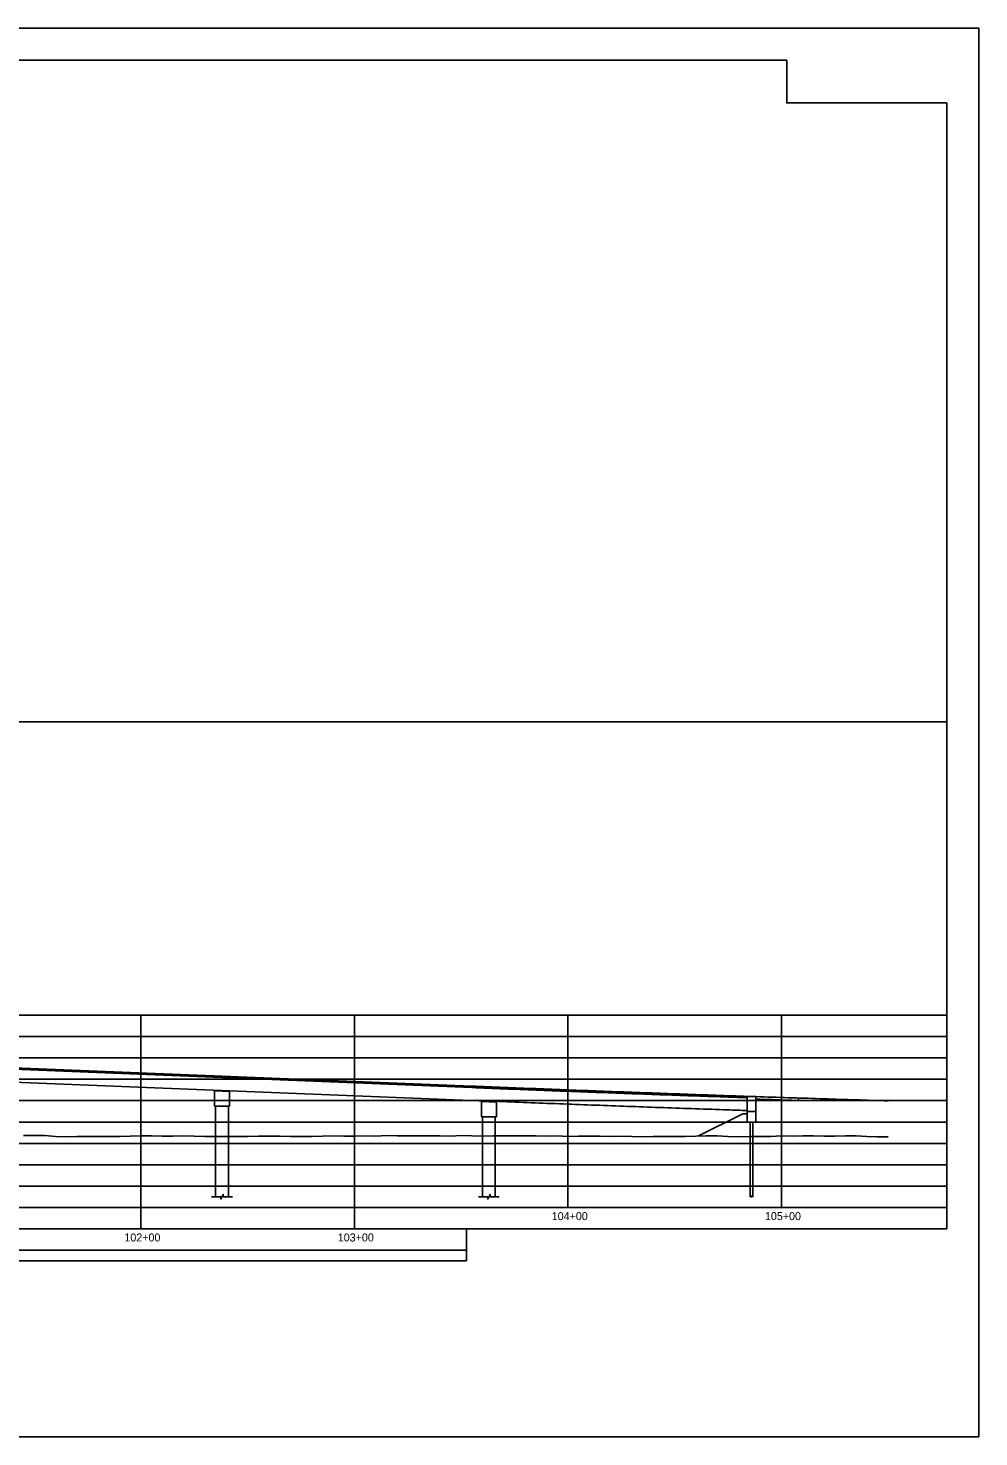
# Model space of a CAD drawing. Extents: x -464 to 4306, y -1372 to 300.
# Drawn here: x 3861 to 4306, y -1372 to -712 of the extents above; entities that cross this region are included whole.
import ezdxf

# ---------------------------------------------------------------- set-up
doc = ezdxf.new("R2010")
doc.units = 0
for name, color, linetype in [('BR_AUTO DIMENSION', 7, 'Continuous'), ('BR_BORDER LINES', 7, 'Continuous'), ('BR_GRID LINES', 7, 'Continuous'), ('BR_TEXT', 7, 'Continuous'), ('Mis Ground Lines', 7, 'Continuous'), ('Miscellaneous Lines', 7, 'Continuous'), ('NOPLOT', 7, 'Continuous'), ('Sheet Plot Border Outside CELL', 7, 'Continuous'), ('sub interior bent cap lines', 7, 'Continuous'), ('Sub Interior Bent Footing Line', 7, 'Continuous'), ('Sub Steel Pile Lines', 7, 'Continuous'), ('Sup Concrete Girder Lines', 7, 'Continuous'), ('Sup Concrete Slab Lines', 7, 'Continuous')]:
    doc.layers.add(name, color=color, linetype=linetype)

msp = doc.modelspace()

# ---------------------------------------------------------------- linework, layer by layer
at = {"layer": 'BR_AUTO DIMENSION'}
for points in [[(3946.62, -1259.94), (3950.94, -1259.94), (3950.94, -1261.06), (3952.06, -1258.83), (3952.06, -1259.94), (3956.37, -1259.94)], [(4071.62, -1259.94), (4075.94, -1259.94), (4075.94, -1261.06), (4077.06, -1258.83), (4077.06, -1259.94), (4081.37, -1259.94)], [(4200.36, -1259.83), (4199.66, -1259.83), (4199.66, -1260.15), (4199.34, -1259.51), (4199.34, -1259.83), (4198.64, -1259.83)]]:
    msp.add_lwpolyline(points, dxfattribs=at)
at = {"layer": 'BR_BORDER LINES'}
msp.add_line((3286, -1037.44), (4291, -1037.44), dxfattribs=at)
at = {"layer": 'BR_GRID LINES'}
for p, q in [((3286, -1174.94), (4291, -1174.94)), ((3913.5, -1274.94), (3913.5, -1174.94)), ((4013.5, -1274.94), (4013.5, -1174.94)), ((4113.5, -1264.94), (4113.5, -1174.94)), ((4213.5, -1264.94), (4213.5, -1174.94)), ((3286, -1184.94), (4291, -1184.94)), ((3286, -1194.94), (4291, -1194.94)), ((3286, -1204.94), (4291, -1204.94)), ((3286, -1214.94), (4291, -1214.94)), ((3286, -1224.94), (4291, -1224.94)), ((3286, -1234.94), (4291, -1234.94)), ((3286, -1244.94), (4291, -1244.94)), ((3286, -1254.94), (4291, -1254.94)), ((3286, -1264.94), (4291, -1264.94)), ((3286, -1274.94), (4066, -1274.94)), ((3286, -1284.94), (4066, -1284.94))]:
    msp.add_line(p, q, dxfattribs=at)
at = {"layer": 'Mis Ground Lines'}
for p, q in [((4195.5, -1221.04), (4174.44, -1231.57)), ((4197.5, -1221.04), (4195.5, -1221.04))]:
    msp.add_line(p, q, dxfattribs=at)
for points in [[(3858.5, -1231.34), (3863.5, -1231.19), (3868.5, -1231.27), (3873.5, -1231.78), (3878.5, -1231.85), (3883.5, -1231.8), (3888.5, -1231.75), (3893.5, -1231.69), (3898.5, -1231.67), (3903.5, -1231.66), (3908.5, -1231.57), (3913.5, -1231.47), (3918.5, -1231.44), (3923.5, -1231.59), (3928.5, -1231.58), (3933.5, -1231.35), (3938.5, -1231.55), (3943.5, -1231.67), (3948.5, -1231.71), (3953.5, -1231.68), (3958.5, -1231.74), (3963.5, -1231.71), (3968.5, -1231.62), (3973.5, -1231.58), (3978.5, -1231.59), (3983.5, -1231.66), (3988.5, -1231.78), (3993.5, -1231.77), (3998.5, -1231.65), (4003.5, -1231.49), (4008.5, -1231.62), (4013.5, -1231.58), (4018.5, -1231.41), (4023.5, -1231.52), (4028.5, -1231.34), (4033.5, -1231.4), (4038.5, -1231.43), (4043.5, -1231.36), (4048.5, -1231.42), (4053.5, -1231.36), (4058.5, -1231.57), (4063.5, -1231.28), (4068.5, -1231.35), (4073.5, -1231.55), (4078.5, -1231.41), (4083.5, -1231.38), (4088.5, -1231.36), (4093.5, -1231.35), (4098.5, -1231.44), (4103.5, -1231.55), (4108.5, -1231.48), (4113.5, -1231.71), (4118.5, -1231.6), (4123.5, -1231.6), (4128.5, -1231.58), (4133.5, -1231.66), (4138.5, -1231.64), (4143.5, -1231.78), (4148.5, -1231.82), (4153.5, -1231.75), (4158.5, -1231.71), (4163.5, -1231.73), (4168.5, -1231.77), (4173.5, -1231.59), (4178.5, -1231.45), (4183.5, -1231.4), (4188.5, -1231.79), (4193.5, -1231.85), (4198.5, -1231.74), (4203.5, -1231.77), (4208.5, -1231.69), (4213.5, -1231.47)], [(4213.5, -1231.47), (4218.5, -1231.56), (4223.5, -1231.46), (4228.5, -1231.42), (4233.5, -1231.54), (4238.5, -1231.6), (4243.5, -1231.44), (4248.5, -1231.48), (4253.5, -1231.8), (4258.5, -1231.81), (4263.5, -1231.82)]]:
    msp.add_lwpolyline(points, dxfattribs=at)
at = {"layer": 'Miscellaneous Lines'}
msp.add_line((4221.5, -1213.7), (4221.5, -1214.86), dxfattribs=at)
msp.add_spline([(4201.5, -1214.2), (4203.46, -1214.27), (4218.46, -1214.77), (4221.5, -1214.86)], degree=3, dxfattribs=at)
at = {"layer": 'NOPLOT'}
msp.add_lwpolyline([(3331, -727.45), (3331, -734.19), (3286, -734.19), (3286, -1357.44), (3831.93, -1357.44), (3831.93, -1289.94), (4066, -1289.94), (4066, -1274.94), (4291, -1274.94), (4291, -747.45), (4216, -747.45), (4216, -727.45)], close=True, dxfattribs=at)
at = {"layer": 'Sheet Plot Border Outside CELL'}
msp.add_lwpolyline([(3226, -712.44), (4306, -712.44), (4306, -1372.44), (3226, -1372.44)], close=True, dxfattribs=at)
at = {"layer": 'sub interior bent cap lines'}
for p, q in [((3948, -1210.33), (3948, -1217.47)), ((3955, -1210.61), (3948, -1210.33)), ((3955, -1210.61), (3955, -1217.47)), ((3948, -1217.47), (3955, -1217.47)), ((3948.5, -1217.47), (3948.5, -1259.94)), ((3954.5, -1217.47), (3954.5, -1259.94)), ((4073, -1215.33), (4073, -1222.47)), ((4080, -1215.61), (4073, -1215.33)), ((4080, -1215.61), (4080, -1222.47)), ((4073, -1222.47), (4080, -1222.47)), ((4073.5, -1222.47), (4073.5, -1259.94)), ((4079.5, -1222.47), (4079.5, -1259.94))]:
    msp.add_line(p, q, dxfattribs=at)
at = {"layer": 'Sub Interior Bent Footing Line'}
for p, q in [((4197.5, -1212.9), (4197.5, -1225.04)), ((4201.5, -1213.04), (4201.5, -1225.04)), ((4201.5, -1220.04), (4197.5, -1220.04)), ((4201.5, -1225.04), (4197.5, -1225.04))]:
    msp.add_line(p, q, dxfattribs=at)
at = {"layer": 'Sub Steel Pile Lines'}
for p, q in [((4198.89, -1225.04), (4198.89, -1259.83)), ((4200.11, -1225.04), (4200.11, -1259.83))]:
    msp.add_line(p, q, dxfattribs=at)
at = {"layer": 'Sup Concrete Girder Lines'}
for p, q in [((3313.5, -1178.61), (4068.47, -1208.81)), ((3313.5, -1184.62), (4068.23, -1214.81))]:
    msp.add_line(p, q, dxfattribs=at)
for points in [[(4068.47, -1208.81), (4083.47, -1209.41), (4098.47, -1209.99), (4113.47, -1210.56), (4128.48, -1211.12), (4143.48, -1211.67), (4158.48, -1212.21), (4173.48, -1212.74), (4188.48, -1213.26), (4197.5, -1213.57)], [(4068.24, -1214.81), (4083.24, -1215.4), (4098.24, -1215.98), (4113.25, -1216.56), (4128.25, -1217.12), (4143.26, -1217.67), (4158.26, -1218.21), (4173.27, -1218.74), (4188.27, -1219.26), (4197.5, -1219.57)]]:
    msp.add_spline(points, degree=3, dxfattribs=at)
at = {"layer": 'Sup Concrete Slab Lines'}
msp.add_line((3313.5, -1177.94), (4068.5, -1208.14), dxfattribs=at)
msp.add_spline([(4068.5, -1208.14), (4083.5, -1208.74), (4098.5, -1209.32), (4113.5, -1209.9), (4128.5, -1210.46), (4143.5, -1211.01), (4158.5, -1211.55), (4173.5, -1212.08), (4188.5, -1212.6), (4203.5, -1213.1), (4218.5, -1213.6), (4233.5, -1214.09), (4248.5, -1214.56), (4263.5, -1215.02)], degree=3, dxfattribs=at)

# ---------------------------------------------------------------- texts
at = {"layer": 'BR_TEXT'}
for s, p in [('104+00', (4105.93, -1270.91)), ('105+00', (4205.81, -1270.91)), ('102+00', (3905.75, -1280.91)), ('103+00', (4005.72, -1280.91))]:
    msp.add_text(s, height=3.75, rotation=360, dxfattribs=at).set_placement(p)

doc.saveas('drawing.dxf')
